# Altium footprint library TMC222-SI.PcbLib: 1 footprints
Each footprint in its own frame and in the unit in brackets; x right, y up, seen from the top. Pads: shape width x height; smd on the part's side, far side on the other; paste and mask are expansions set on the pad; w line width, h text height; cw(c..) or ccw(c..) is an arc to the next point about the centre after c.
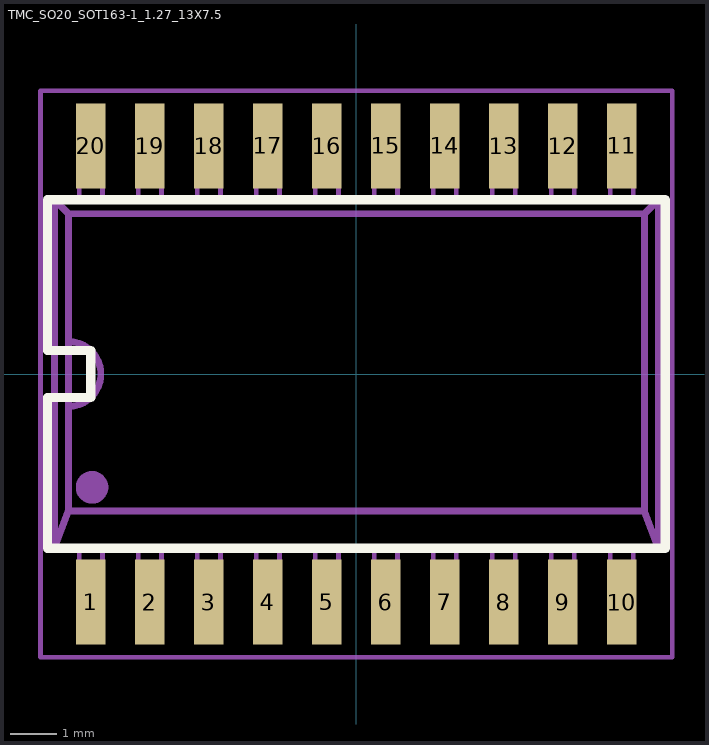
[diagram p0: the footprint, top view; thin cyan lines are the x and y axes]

## TMC_SO20_SOT163-1_1.27_13X7.5 [mm]
pads (20):
  rect 0.64x1.83 smd paste-0.002: 1(-5.715,-4.912) 2(-4.445,-4.912) 3(-3.175,-4.912) 4(-1.905,-4.912) 5(-0.635,-4.912) 6(0.635,-4.912) 7(1.905,-4.912) 8(3.175,-4.912) 9(4.445,-4.912) 10(5.715,-4.912) 11(5.715,4.912) 12(4.445,4.912) 13(3.175,4.912) 14(1.905,4.912) 15(0.635,4.912) 16(-0.635,4.913) 17(-1.905,4.912) 18(-3.175,4.912) 19(-4.445,4.912) 20(-5.715,4.912)
L26-Silk Screen Top (Multiple PADS layers...):
  lines w0.2: -6.65,-3.75 6.65,-3.75 6.65,3.75 -6.65,3.75 -6.65,0.508 -5.715,0.508 -5.715,-0.508 -6.65,-0.508 -6.65,-3.75
L13:
  circle w0.5: c-5.69,-2.44 r0.1
  lines w0.1: -5.965,-3.75 -5.965,-5.3 -5.465,-5.3 -5.465,-3.75 ; -5.965,3.75 -5.965,5.3 -5.465,5.3 -5.465,3.75 ; -4.695,-3.75 -4.695,-5.3 -4.195,-5.3 -4.195,-3.75 ; -4.695,3.75 -4.695,5.3 -4.195,5.3 -4.195,3.75 ; -3.425,-3.75 -3.425,-5.3 -2.925,-5.3 -2.925,-3.75 ; -3.425,3.75 -3.425,5.3 -2.925,5.3 -2.925,3.75 ; -2.155,-3.75 -2.155,-5.3 -1.655,-5.3 -1.655,-3.75 ; -2.155,3.75 -2.155,5.3 -1.655,5.3 -1.655,3.75 ; -0.885,-3.75 -0.885,-5.3 -0.385,-5.3 -0.385,-3.75 ; -0.885,3.75 -0.885,5.3 -0.385,5.3 -0.385,3.75 ; 0.385,-3.75 0.385,-5.3 0.885,-5.3 0.885,-3.75 ; 0.385,3.75 0.385,5.3 0.885,5.3 0.885,3.75 ; 1.655,-3.75 1.655,-5.3 2.155,-5.3 2.155,-3.75 ; 1.655,3.75 1.655,5.3 2.155,5.3 2.155,3.75 ; 2.925,-3.75 2.925,-5.3 3.425,-5.3 3.425,-3.75 ; 2.925,3.75 2.925,5.3 3.425,5.3 3.425,3.75 ; 4.195,-3.75 4.195,-5.3 4.695,-5.3 4.695,-3.75 ; 4.195,3.75 4.195,5.3 4.695,5.3 4.695,3.75 ; 5.465,-3.75 5.465,-5.3 5.965,-5.3 5.965,-3.75 ; 5.465,3.75 5.465,5.3 5.965,5.3 5.965,3.75
  lines w0.15: -6.5,-3.75 -6.2,-2.95 ; -6.5,-3.75 -6.5,3.75 ; -6.5,-3.75 6.5,-3.75 ; -6.5,3.75 -6.2,3.45 ; -6.5,3.75 6.5,3.75 ; -6.2,-2.95 -6.2,-0.7 ; -6.2,-2.95 6.2,-2.95 ; -6.2,-0.7 ccw(c-6.2,0) -6.2,0.7 ; -6.2,-0.7 -6.2,0.7 ; -6.2,0.7 -6.2,3.45 ; -6.2,3.45 6.2,3.45 ; 6.2,-2.95 6.5,-3.75 ; 6.2,-2.95 6.2,3.45 ; 6.2,3.45 6.5,3.75 ; 6.5,-3.75 6.5,3.75
L15 (Multiple PADS layers...):
  lines w0.1: -6.8,-6.1 -6.8,6.1 6.8,6.1 6.8,-6.1 -6.8,-6.1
